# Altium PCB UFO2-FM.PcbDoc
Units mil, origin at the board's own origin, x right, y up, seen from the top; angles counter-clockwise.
Board outline 2125.98 x 1889.76 mil, 2 copper layers (Top Layer, Bottom Layer), stack 63.824 mil thick; 93 components, 51 nets, 265 pads, 112 vias.
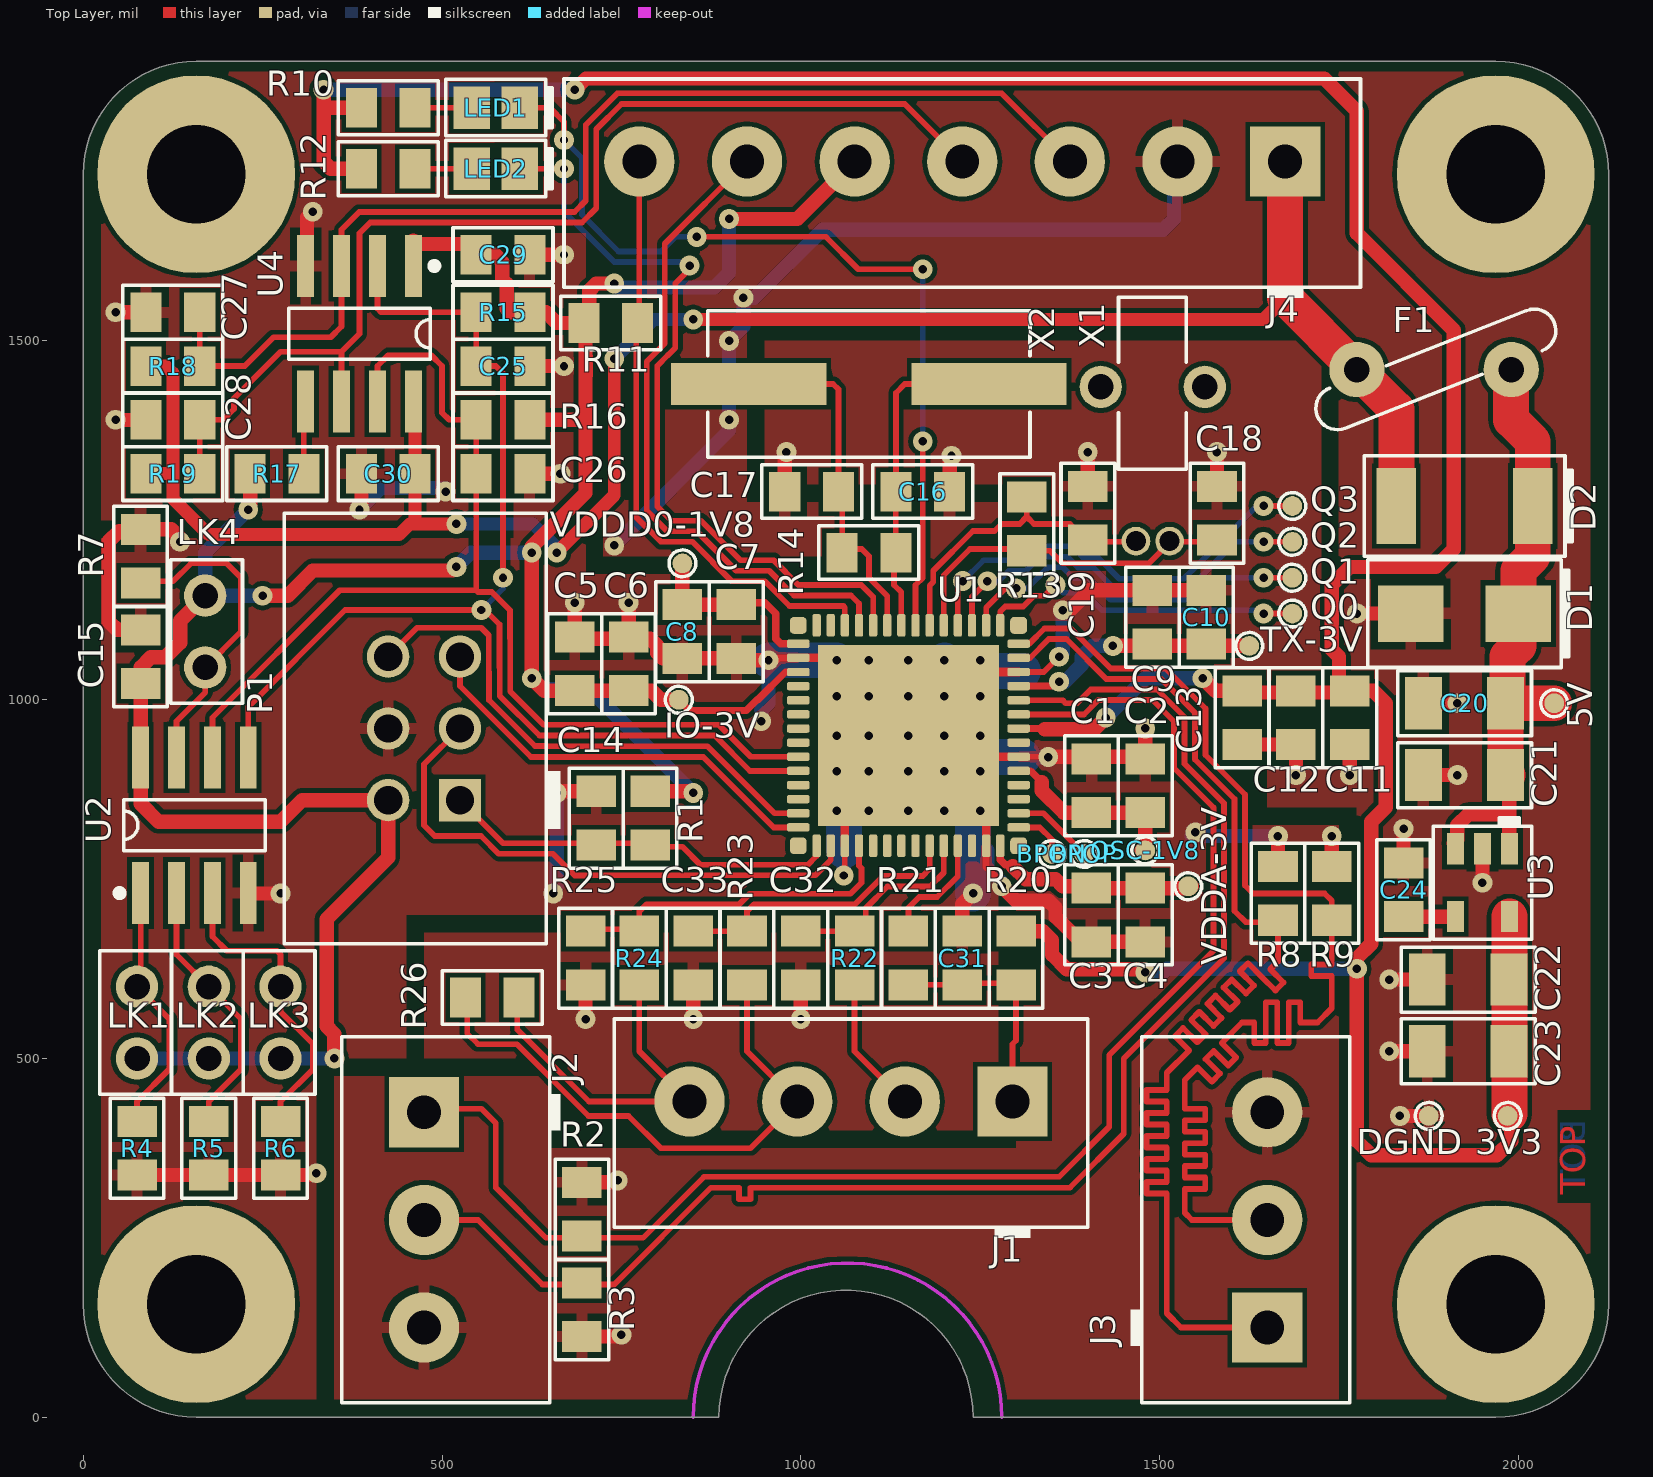
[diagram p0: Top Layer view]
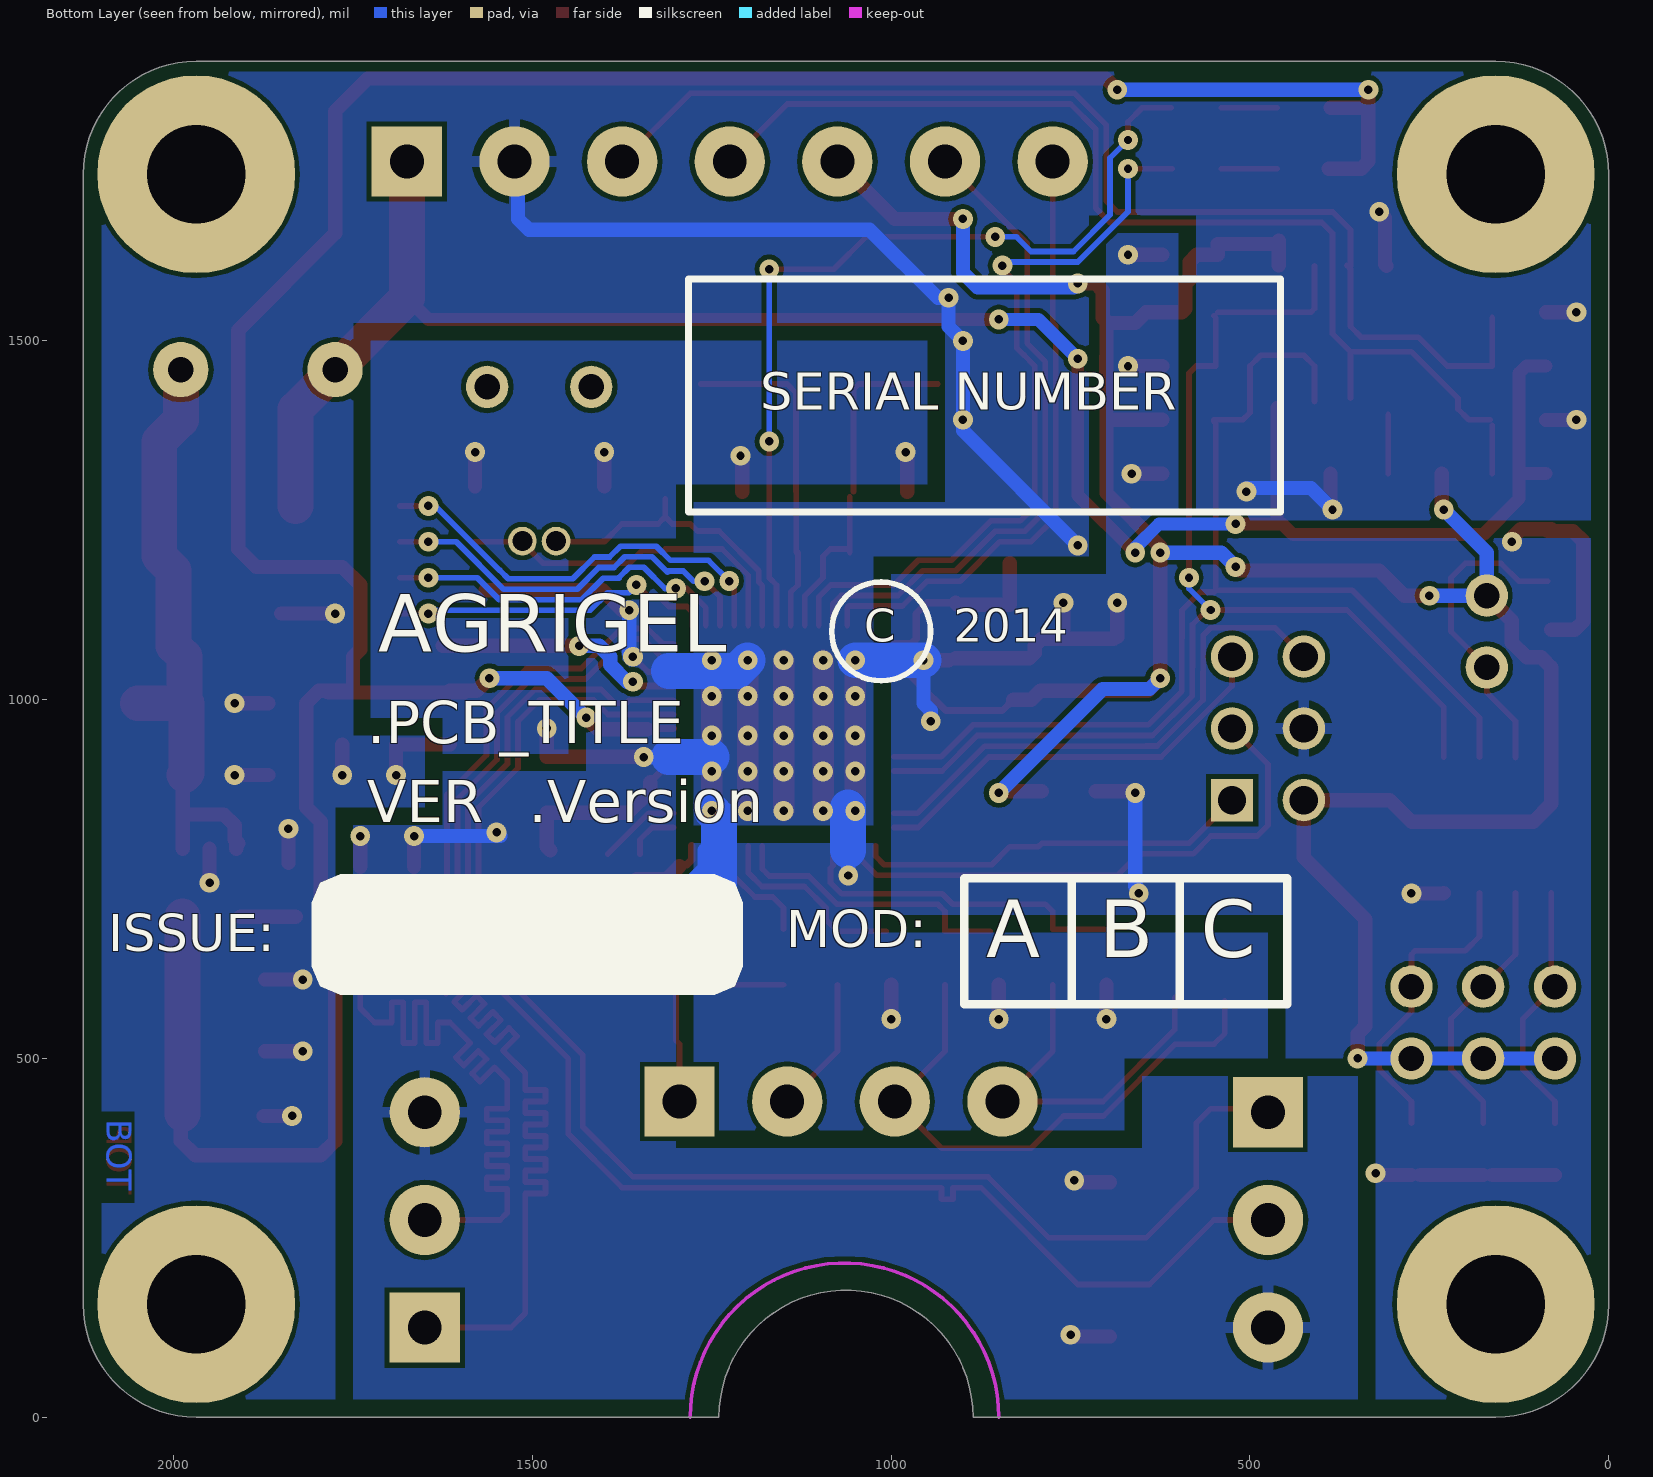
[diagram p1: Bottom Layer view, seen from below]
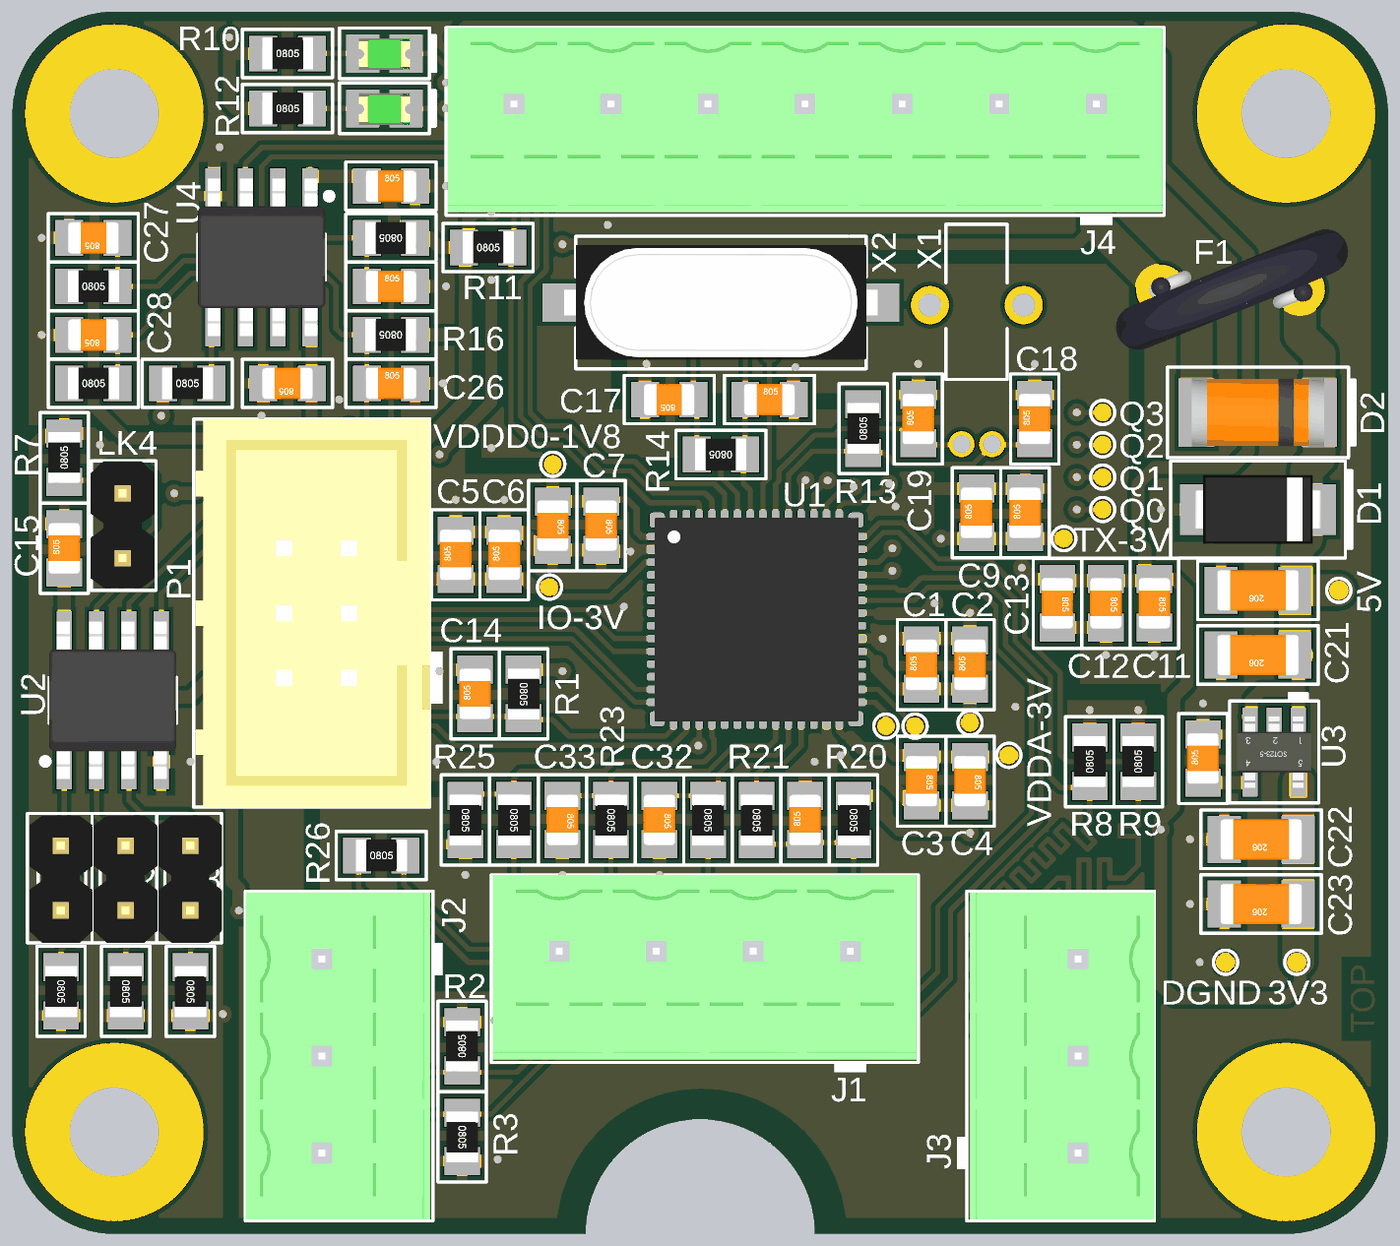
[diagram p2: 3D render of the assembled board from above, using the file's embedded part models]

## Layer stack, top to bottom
Top Layer: signal copper 1.4
Dielectric: prepreg 61.0236, FR-4, Dk 4.2
Bottom Layer: signal copper 1.4

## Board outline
0,157.48 ccw(c157.48,157.48) 157.48,0 157.48,0.01 885.83,0 cw(c1062.99,0) 1240.16,0 1968.5,0 ccw(c1968.5,157.48) 2125.98,157.48 2125.98,1732.28 ccw(c1968.5,1732.28) 1968.5,1889.76 157.48,1889.76 ccw(c157.48,1732.28) 0,1732.28

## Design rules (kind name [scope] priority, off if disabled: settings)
Clearance [All] p1: gap=6.69
ComponentClearance [All] p1: gap=0 collisioncheckmode=3 verticalgap=1 showdistances=FALSE
FabricationTestPointUsage TestPointUsage [All] p1: valid=0 allowmultiple=FALSE
FabricationTestpoint Testpoint [All] p1: side=3 testpointundercomponent=TRUE minsize=40 maxsize=100 preferedsize=60 minholesize=0 maxholesize=40 preferedholesize=32 testpointgrid=1 allowsidetop=TRUE allowsidebottom=TRUE usegrid=TRUE gridtolerance=0.01
HoleSize [All] p1: absolutevalues=TRUE maxlimit=196.85 minlimit=9.84 maxpercent=80.000 minpercent=20.000
Length "Schematic Length Constraint_3" [InNet('TX3')] p1: maxlimit=2050 minlimit=2030
Length "Schematic Length Constraint_2" [InNet('TX2')] p2: maxlimit=2050 minlimit=2030
Length "Schematic Length Constraint_1" [InNet('TX1')] p3: maxlimit=2050 minlimit=2030
Length "Schematic Length Constraint" [InNet('TX0')] p4: maxlimit=2050 minlimit=2030
PlaneClearance [All] p1: clearance=19.68
PolygonConnect PolygonConnect_1 [All vs IsNamedPolygon('Bot - DGND-Direct')] p1: connectstyle=Direct reliefconductorwidth=10 reliefentries=4 polygonreliefangle="90 Angle" airgapwidth=10
PolygonConnect PolygonConnectVia [All vs isvia] p2: connectstyle=Direct reliefconductorwidth=9.84 reliefentries=4 polygonreliefangle="90 Angle" airgapwidth=10
PolygonConnect [All] p3: connectstyle=Relief reliefconductorwidth=15.75 reliefentries=4 polygonreliefangle="90 Angle" airgapwidth=10
RoutingCorners [All] p1: cornerstyle=45-Degree minsetback=98.43 maxsetback=98.43
RoutingVias [All] p1: holewidth=11.81 width=27.56 viastyle="Through Hole" minholewidth=11.81 minwidth=27.56 maxholewidth=11.81 maxwidth=27.56
ShortCircuit LK5 [(InNet('DGND') AND InComponent('LK5'))] p1: allowed=TRUE
ShortCircuit LK6 [(InNet('DGND') AND InComponent('LK6'))] p2: allowed=TRUE
ShortCircuit LK7 [(InNet('DGND') AND InComponent('LK7'))] p3: allowed=TRUE
ShortCircuit LK8 [(InNet('DGND') AND InComponent('LK8'))] p4: allowed=TRUE
ShortCircuit LK9 [(InNet('DGND') AND InComponent('LK9'))] p5: allowed=TRUE
ShortCircuit [All] p6: allowed=FALSE
SilkToSolderMaskClearance SilkscreenOverComponentPads [IsPad] p1: minsilkscreentomaskgap=10 clearancetoexposedcopper=TRUE
SolderMaskExpansion [All] p1: expansion=1.97
Width "Width_High Power" [InNetClass('High Power')] p1: maxlimit=59.06 minlimit=19.68 preferedwidth=39.37
Width Width_Power [InNetClass('Power')] p2: maxlimit=39.37 minlimit=11.81 preferedwidth=19.68
Width [All] p3: maxlimit=78.74 minlimit=7.87 preferedwidth=7.87
20 further rules are at their usual default settings.

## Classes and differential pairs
component class UFO2-FM: VDDD0-1V8

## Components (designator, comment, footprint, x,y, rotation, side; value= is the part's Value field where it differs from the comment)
3V3 "TP-SMD-0.7MM_V" TP-SMD-0.7MM 1985,420 r90 top
5V "TP-SMD-0.7MM_V" TP-SMD-0.7MM 2050,995 r90 top
BPON "TP-SMD-0.7MM" TP-SMD-0.7MM 1350,785 r270 top
BPOP "TP-SMD-0.7MM" TP-SMD-0.7MM 1395,785 r270 top
C1 "4.7uF_C0805_10V_10%_X5R" CAPC0805X110N 1405,880 r90 top
C2 "100nF_C0805_50V_10%_X7R" CAPC0805X110N 1480,880 r90 top
C3 "4.7uF_C0805_10V_10%_X5R" CAPC0805X110N 1405,700 r270 top
C4 "100nF_C0805_50V_10%_X7R" CAPC0805X110N 1480,700 r270 top
C5 "4.7uF_C0805_10V_10%_X5R" CAPC0805X110N 685,1050 r90 top
C6 "100nF_C0805_50V_10%_X7R" CAPC0805X110N 760,1050 r90 top
C7 "4.7uF_C0805_10V_10%_X5R" CAPC0805X110N 910,1095 r270 top
C8 "100nF_C0805_50V_10%_X7R" CAPC0805X110N 835,1095 r270 top
C9 "4.7uF_C0805_10V_10%_X5R" CAPC0805X110N 1490,1115 r90 top
C10 "100nF_C0805_50V_10%_X7R" CAPC0805X110N 1565,1115 r90 top
C11 "4.7uF_C0805_10V_10%_X5R" CAPC0805X110N 1765,975 r270 top
C12 "4.7uF_C0805_10V_10%_X5R" CAPC0805X110N 1690,975 r270 top
C13 "100nF_C0805_50V_10%_X7R" CAPC0805X110N 1615,975 r270 top
C14 "100nF_C0805_50V_10%_X7R" CAPC0805X110N 715,835 r90 top
C15 "100nF_C0805_50V_10%_X7R" CAPC0805X110N 80,1060 r90 top
C16 "22pF_C0805_50V_10%_X7R" CAPC0805X110N 1170,1290 r0 top
C17 "22pF_C0805_50V_10%_X7R" CAPC0805X110N 1015,1290 r180 top
C18 "22pF_C0805_50V_10%_X7R" CAPC0805X110N 1580,1260 r90 top
C19 "22pF_C0805_50V_10%_X7R" CAPC0805X110N 1400,1260 r90 top
C20 "10uF_C1206_16V_5%_X7R" CAPC1206X178N 1925,995 r180 top
C21 "10uF_C1206_16V_5%_X7R" CAPC1206X178N 1925,895 r180 top
C22 "10uF_C1206_16V_5%_X7R" CAPC1206X178N 1930,610 r180 top
C23 "10uF_C1206_16V_5%_X7R" CAPC1206X178N 1930,510 r180 top
C24 "10nF_C0805_50V_10%_X7R" CAPC0805X110N 1840,735 r90 top
C25 "10nF_C0805_50V_10%_X7R" CAPC0805X110N 585,1465 r0 top
C26 "10nF_C0805_50V_10%_X7R" CAPC0805X110N 585,1315 r0 top
C27 "10nF_C0805_50V_10%_X7R" CAPC0805X110N 125,1540 r180 top
C28 "10nF_C0805_50V_10%_X7R" CAPC0805X110N 125,1390 r180 top
C29 "10nF_C0805_50V_10%_X7R" CAPC0805X110N 585,1620 r0 top
C30 "10nF_C0805_50V_10%_X7R" CAPC0805X110N 425,1315 r180 top
C31 "10nF_C0805_50V_10%_X7R" CAPC0805X110N 1225,640 r90 top
C32 "10nF_C0805_50V_10%_X7R" CAPC0805X110N 1000,640 r270 top
C33 "10nF_C0805_50V_10%_X7R" CAPC0805X110N 850,640 r270 top
D1 "SK110_SMA" SMA 1925,1120 r180 top
D2 "SM4007-DNF" DO-213AB 1925,1270 r180 top
DGND "TP-SMD-0.7MM_V" TP-SMD-0.7MM 1875,420 r180 top
F1 "MF-R050" MF-R110 1885,1460 r0 top
IO-3V "TP-SMD-0.7MM_V" TP-SMD-0.7MM 830,1000 r180 top
J1 "ECH381V-04P" ECH381V-04P 1070,440 r0 top
J2 "ECH381V-03P" ECH381V-03P 475,275 r90 top
J3 "ECH381V-03P" ECH381V-03P 1650,275 r270 top
J4 "ECH381V-07P" ECH381V-07P 1225,1750 r0 top
LED1 "GREEN_0805_SMD" LED0805-Green 575,1825 r180 top
LED2 "GREEN_0805_SMD" LED0805-Green 575,1740 r180 top
LK1 "Link-THP-2.54-2PIN" Link-THP-2.54-2PIN 75,550 r90 top
LK2 "Link-THP-2.54-2PIN" Link-THP-2.54-2PIN 175,550 r90 top
LK3 "Link-THP-2.54-2PIN" Link-THP-2.54-2PIN 275,550 r90 top
LK4 "Link-THP-2.54-2PIN" Link-THP-2.54-2PIN 170,1095 r270 top
OSC-1V8 "TP-SMD-0.7MM_V" TP-SMD-0.7MM 1480,790 r90 top
P1 "09185066324" 09185066324 475,960 r90 top
Q0 "TP-SMD-0.7MM" TP-SMD-0.7MM 1685,1120 r270 top
Q1 "TP-SMD-0.7MM" TP-SMD-0.7MM 1685,1170 r180 top
Q2 "TP-SMD-0.7MM" TP-SMD-0.7MM 1685,1220 r270 top
Q3 "TP-SMD-0.7MM" TP-SMD-0.7MM 1685,1270 r270 top
R1 "39K_R0805_1%" RESC0805X65N 790,835 r270 top
R2 "100R_R0805_1%" RESC0805X65N 695,290 r90 top
R3 "100R_R0805_1%" RESC0805X65N 695,150 r270 top
R4 "10K_R0805_1%" RESC0805X65N 75,375 r270 top
R5 "10K_R0805_1%" RESC0805X65N 175,375 r270 top
R6 "10K_R0805_1%" RESC0805X65N 275,375 r270 top
R7 "10K_R0805_1%" RESC0805X65N 80,1200 r90 top
R8 "100R_R0805_1%" RESC0805X65N 1665,730 r90 top
R9 "100R_R0805_1%" RESC0805X65N 1740,730 r90 top
R10 "3K_R0805_1%" RESC0805X65N 425,1825 r0 top
R11 "10K_R0805_1%" RESC0805X65N 735,1525 r0 top
R12 "3K_R0805_1%" RESC0805X65N 425,1740 r0 top
R13 "10M_R0805_1%" RESC0805X65N 1315,1245 r90 top
R14 "1M_R0805_1%" RESC0805X65N 1095,1205 r180 top
R15 "10K_R0805_1%" RESC0805X65N 585,1540 r180 top
R16 "10K_R0805_1%" RESC0805X65N 585,1390 r180 top
R17 "10K_R0805_1%" RESC0805X65N 270,1315 r0 top
R18 "10K_R0805_1%" RESC0805X65N 125,1465 r0 top
R19 "10K_R0805_1%" RESC0805X65N 125,1315 r0 top
R20 "0R[NEQ]_R0805_1%" RESC0805X65N 1300,640 r270 top
R21 "0R_R0805_1%" RESC0805X65N 1150,640 r270 top
R22 "2K7_R0805_1%" RESC0805X65N 1075,640 r270 top
R23 "2K7_R0805_1%" RESC0805X65N 925,640 r270 top
R24 "1K_R0805_0.1%" RESC0805X65N 775,640 r270 top
R25 "1K5_R0805_1%" RESC0805X65N 700,640 r270 top
R26 "0R[NEQ]_R0805_1%" RESC0805X65N 570,585 r0 top
TX-3V "TP-SMD-0.7MM_V" TP-SMD-0.7MM 1625,1075 r90 top
U1 "UFO2" QFN56-8x8-EP 1150,950 r0 top
U2 "24LC256-I/SN" SO8 155,825 r90 top
U3 "LP2992IM5X-5.0" SOT23-5 1950,745 r270 top
U4 "PCA9512AD" SO8 385,1510 r270 top
VDDA-3V "TP-SMD-0.7MM_V" TP-SMD-0.7MM 1540,740 r90 top
VDDD0-1V8 "TP-SMD-0.7MM_V" TP-SMD-0.7MM 835,1190 r90 top
X1 "32.768kHz" MMTF32 1490,1435 r0 top
X2 "XTAL_16.00MHz-ACT-HC49/US-SMX" HC49/US-SMX-4.2 1095,1440 r180 top

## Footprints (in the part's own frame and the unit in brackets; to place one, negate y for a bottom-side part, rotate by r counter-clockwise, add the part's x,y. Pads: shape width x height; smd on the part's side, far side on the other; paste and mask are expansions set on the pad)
09185066324 [mil] "09185066324 2.54mm"
  rect 59x59 hole 39.37: 1(-100,-50)
  round 59 hole 39.37: 2(-100,50) 3(0,-50) 4(0,50) 5(100,-50) 6(100,50)
  silkscreen extent -300,-190 300,195, body extent -300,-170 300,192, height 373
CAPC0805X110N [mm] "Chip Capacitor, 0805, 2-Leads, Body 2.0x1.3mm, IPC Medium Density"
  rect 1.1x1.4 smd paste+0 mask+0.05: 1(-0.95,0) 2(0.95,0)
  silkscreen extent -1.77,-0.95 1.77,0.95, body extent -1,-0.62 1,0.63, height 1.11
CAPC1206X178N [mm] "Chip Capacitor, 1206, 2-Leads, Body 3.2x1.6mm, IPC Medium Density"
  rect 1.3x1.85 smd paste+0 mask+0.05: 1(-1.45,0) 2(1.45,0)
  silkscreen extent -2.37,-1.15 2.37,1.15, body extent -1.6,-0.8 1.6,0.8, height 1.77
DO-213AB [mil] "DO-213AB 5.0x2.5mm"
  rect 55x106 smd mask+1: 1(-95,0) 2(95,0)
  silkscreen extent -150,-70 140,70, body extent -102,-53 102,53, height 106
ECH381V-03P [mil] "ECH381V-03P 12.22x7.0mm"
  rect 98x98 hole 47.24: 1(150,0)
  round 98 hole 47.24: 2(0,0) 3(-150,0)
  silkscreen extent -255,-190 255,115, body extent -252,-170 252,115, height 362
ECH381V-04P [mil] "ECH381V-04P 19.84x7.0mm"
  rect 98x98 hole 47.24: 1(225,0)
  round 98 hole 47.24: 2(75,0) 3(-75,0) 4(-225,0)
  silkscreen extent -330,-190 330,115, body extent -327,-170 327,115, height 362
ECH381V-07P [mil] "ECH381V-07P 31.27x7.0mm"
  rect 98x98 hole 47.24: 1(450,0)
  round 98 hole 47.24: 2(300,0) 3(150,0) 4(0,0) 5(-150,0) 6(-300,0) 7(-450,0)
  silkscreen extent -555,-190 555,115, body extent -552,-170 552,115, height 362
HC49/US-SMX-4.2 [mm] "XTAL-HC49/US-SMX, 2-Leads, Body 11.1x4.83mm (max), Pitch 4.3mm"
  rect 5.5x1.5 smd paste+0 mask+0.025: 1(-4.25,0) 2(4.25,0)
  silkscreen extent -5.7,-2.6 5.7,2.6, body extent -6.15,-2.25 6.15,2.25, height 5.18
LED0805-Green [mm] "LED, 0805, 2-Leads, Body 2.0x1.3mm, IPC Medium Density"
  rect 1.3x1.5 smd paste+0 mask+0.025: 1(-0.85,0) 2(0.85,0)
  silkscreen extent -2,-1 1.77,0.99, body extent -1.01,-0.6 1.01,0.65, height 1.2
Link-THP-2.54-2PIN [mil] "Link THP 2.54mm"
  round 59 hole 35.43: 1(-50,0) 2(50,0)
  silkscreen extent -100,-48 100,52, body extent -100,-49 96,49, height 323
MF-R110 [mil] "MF-R110 8.9x3.0mm"
  round 77 hole 35.43: 1(-110,0) 2(105,0)
  silkscreen extent -167,-84 167,84, body extent -200,-127 200,127, height 624
MMTF32 [mil] "MMTF 6.0x2.0mm"
  round 40 hole 27.56: 1(-23,-214) 2(24,-214)
  round 59 hole 35.43: M1(-72,1) M2(73,1)
  silkscreen extent -47,-114 47,126, body extent -47,-226 47,126, height 94
QFN56-8x8-EP [mm] "QFN 56 8.0x8.0mm"
  rrect50% 0.8x0.3 smd mask+0.025: 1(-3.9,3.25) 2(-3.9,2.75) 3(-3.9,2.25) 4(-3.9,1.75) 5(-3.9,1.25) 6(-3.9,0.75) 7(-3.9,0.25) 8(-3.9,-0.25) 9(-3.9,-0.75) 10(-3.9,-1.25) 11(-3.9,-1.75) 12(-3.9,-2.25) 13(-3.9,-2.75) 14(-3.9,-3.25) 29(3.9,-3.25) 30(3.9,-2.75) 31(3.9,-2.25) 32(3.9,-1.75) 33(3.9,-1.25) 34(3.9,-0.75) 35(3.9,-0.25) 36(3.9,0.25) 37(3.9,0.75) 38(3.9,1.25) 39(3.9,1.75) 40(3.9,2.25) 41(3.9,2.75) 42(3.9,3.25)
  rrect50% 0.3x0.8 smd mask+0.025: 15(-3.25,-3.9) 16(-2.75,-3.9) 17(-2.25,-3.9) 18(-1.75,-3.9) 19(-1.25,-3.9) 20(-0.75,-3.9) 21(-0.25,-3.9) 22(0.25,-3.9) 23(0.75,-3.9) 24(1.25,-3.9) 25(1.75,-3.9) 26(2.25,-3.9) 27(2.75,-3.9) 28(3.25,-3.9) 43(3.25,3.9) 44(2.75,3.9) 45(2.25,3.9) 46(1.75,3.9) 47(1.25,3.9) 48(0.75,3.9) 49(0.25,3.9) 50(-0.25,3.9) 51(-0.75,3.9) 52(-1.25,3.9) 53(-1.75,3.9) 54(-2.25,3.9) 55(-2.75,3.9) 56(-3.25,3.9)
  rect 6.4x6.4 smd paste-3.5 mask+0.025: 57(0,0)
  rrect50% 0.6x0.6 smd mask+0.025: C1(-3.9,3.9) C2(-3.9,-3.9) C3(3.9,-3.9) C4(3.9,3.9)
  body extent -4,-4 4,4, height 0.77
RESC0805X65N [mm] "Chip Resistor, 0805, 2-Leads, Body 2.0x1.3mm, IPC Medium Density"
  rect 1.1x1.4 smd paste+0 mask+0.05: 1(-0.95,0) 2(0.95,0)
  silkscreen extent -1.77,-0.95 1.77,0.95, body extent -0.99,-0.62 1.01,0.63, height 0.6
SMA [mil] "SMA 5.6x2.95mm"
  rect 91x79 smd mask+0.98: 1(-75,0.08) 2(75,0.08)
  silkscreen extent -145,-75 135,75, body extent -98,-53 98,53, height 85
SO8 [mm] "SOIC, 8-Leads, Body 5.0x4.0mm (max), Pitch 1.27mm, IPC Medium Density"
  rect 2.2x0.6 smd paste+0 mask+0.05: 1(-2.4,1.905) 2(-2.4,0.635) 3(-2.4,-0.635) 4(-2.4,-1.905) 5(2.4,-1.905) 6(2.4,-0.635) 7(2.4,0.635) 8(2.4,1.905)
  silkscreen extent -2.52,-2.5 0.9,2.77, body extent -3.1,-2.5 3.1,2.5, height 1.78
SOT23-5 [mm] "SOT23, 5-Leads, Body 3.0x3.0mm (max), Pitch 0.95mm, IPC Medium Density"
  rect 1.1x0.6 smd paste+0 mask+0.05: 1(-1.2,0.95) 2(-1.2,0) 3(-1.2,-0.95) 4(1.2,-0.95) 5(1.2,0.95)
  silkscreen extent -2.3,-1.75 2,1.75, body extent -1.4,-1.45 1.4,1.45, height 1.14
TP-SMD-0.7MM [mm] "Test Point, SMD, 0.7mm"
  round 0.7 smd paste-1 mask+0.025: 1(0,0)
  silkscreen extent -0.47,-0.48 0.47,0.47, body extent -0.35,-0.35 0.35,0.35, height 0.01

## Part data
3V3 5V BPON BPOP DGND IO-3V OSC-1V8 Q0 Q1 Q2 Q3 TX-3V VDDA-3V VDDD0-1V8: "Test Point Surface Mount 0.7mm Pad"
C1 C3 C5 C7 C9 C11 C12: library part 4.7uF_0805N_10V_10%_X5R_V, "Cap Ceramic X5R"
C2 C4 C6 C8 C10 C13 C14 C15: library part 100nF_0805N_50V_10%_X7R_V, "Cap Ceramic X7R"
C16 C17 C18 C19: library part 22pF_0805N_50V_10%_X7R_V, "Cap Ceramic X7R"
C20 C21 C22 C23: library part 10uF_1206N_16V_5%_X7R_V, "Cap Ceramic X7R"
C24 C25 C26 C27 C28 C29 C30 C31 C32 C33: library part 10nF_0805N_50V_10%_X7R_V, "Cap Ceramic X7R"
D1: library part SK110_SMA_V, "Diode Schottky Rectifier 1Amp 100V"
D2: library part SM4007_H-DNF, "Diode Rectifier 1Amp 1000V - Do no Fit"
F1: library part PolyFuse-MF-R050, "PTC Resettable Fuse 500mA 60V"
J1 J2 J3 J4: "Header Pluggable 3.81mm Vertical"
LED1 LED2: library part GREEN_0805_SMD_H, "LED SMD 0805 Green"
LK1 LK2 LK3 LK4: "Link THP Open 2.54mm"
P1: "Header Box Male Straight 2.54mm Pitch"
R1: library part 39K_0805_V, "Resistor Chip SMD"
R2 R3 R8 R9: library part 100R_0805_V, "Resistor Chip SMD"
R4 R5 R6 R7 R11 R15 R16 R17 R18 R19: library part 10K_0805_V, "Resistor Chip SMD"
R10 R12: library part 3K_0805_H, "Resistor Chip SMD"
R13: library part 10M_0805_H, "Resistor Chip SMD"
R14: library part 1M_0805_H, "Resistor Chip SMD"
R20 R26: library part 0R_0805_H-DNF, "Resistor Chip SMD - Do not Fit"
R21: library part 0R_0805_H, "Resistor Chip SMD"
R22 R23: library part 2K7_0805_H, "Resistor Chip SMD"
R24: library part 1K_0805_H-0.1%, "Resistor Chip SMD"
R25: library part 1K5_0805_V, "Resistor Chip SMD"
U1: library part UFO2_QFN56, "IC D-Flow ASIC"
U2: library part 24LC256-I/SN-SO8, "IC 256K I2C Serial EEPROM"
U3: library part LP2992IM5X-5.0_SOT23-5N, "Voltage Regulator Ultra LDO 250mA"
U4: library part PCA9512AD_SO8, "IC Level-Shifting I2C Bus and SMBus Buffer"
X1: library part XTAL_32.768kHz_MMTF32, "Crystal - MMTF32"
X2: "Crystal - ACT HC49/US-SMX"

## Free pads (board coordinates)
  round 275.59 hole 137.8 unplated mask+1: 0(157.48,157.48) 1(1968.5,157.48) 2(1968.5,1732.28) 3(157.48,1732.28)

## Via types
v1: diameter 27.56, hole 11.81, Top Layer to Bottom Layer, tented both sides, 112 vias

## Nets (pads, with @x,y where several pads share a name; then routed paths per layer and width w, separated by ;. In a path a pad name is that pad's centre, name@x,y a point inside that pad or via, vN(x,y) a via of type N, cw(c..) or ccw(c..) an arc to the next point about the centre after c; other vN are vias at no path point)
+3V3: 3V3.1 C11.1 C12.1 C13.1 C22.1 C23.1 R10.1 R12.1 R20.1 U1.36 U3.5 | length 4992.2
  Top Layer w10: U1.36 1341.96,959.84 ; 1341.96,955.06 1345.21,955.06 1348.99,958.83
  Top Layer w20: v1(335,1850) 335,1825 ; R10.1 335,1825 ; R12.1@390,1740 R12.1 345,1740 335,1750 335,1825 ; v1(685,1850) 700.69,1865.69 1729.31,1865.69 1775,1820 1775,1650 1910,1515 1910,1210 1885,1185 1765,1185 1740,1160 1740,1070 1750,1060 1750,1012.4 C11.1 1797.6,1012.4 1815,995 1815,850 1795,830 1795,660 1775,640 v1(1775,625) 1775,385 1795,365 1970,365 1990,385 3V3.1@1990,425 ; R20.1 1337.6,677.4 1350,665 1350,644.78 1370.53,624.25 1475.75,624.25 v1(1480,620) ; 1340,958.83 1348.99,958.83 1408.83,958.83 v1(1425,975) ; v1(1560,1030) 1577.6,1012.4 C13.1 ; C13.1@1595,1010 C11.1@1784.53,1010
  Top Layer w50: 3V3.1@1987.4,422.4 U3.5
  Bottom Layer w20: v1(335,1850) v1(685,1850) ; v1(1425,975) 1480,1030 v1(1560,1030) ; v1(1480,620) 1505,620 1510,625 v1(1775,625)
+5V: 5V.1 C20.1 C21.1 D1.1 D2.1 F1.2 U3.1 U3.3 | length 877.9
  Top Layer w20: U3.3@1910,800 U3.3@1912.6,802.6 ; U3.3 U3.3@1912.6,802.6 ; C21.1@1980,890 1987.4,882.6 1987.4,840 ; C21.1 C21.1@1985,895 ; U3.1 1987.4,840 ; U3.3@1912.6,802.6 1915,805 1915,825 1930,840 1987.4,840
  Top Layer w50: C20.1 1982.09,897.91 C21.1@1985,895 ; F1.2 1990,1390 2020,1360 D2.1 2020,1200 2000,1180 D1.1 2000,1075 1985,1060 1985,995 5V.1
DGND: C1.2 C2.2 C3.2 C4.2 C5.2 C6.2 C7.2 C8.2 C9.2 C10.2 C11.2 C12.2 C13.2 C14.2 C15.2 C16.2 C17.2 C18.2 C19.2 C20.2 C21.2 C22.2 C23.2 C24.2 C25.2 C26.2 C27.2 C28.2 C29.2 C30.2 C31.2 C32.2 C33.2 D1.2 DGND.1 J2.3 J3.3 J4.2 P1.4 R2.2 R3.2 R4.2 R5.2 R6.2 R7.2 R8.2 R9.2 R25.2 U1.2 U1.17 U1.27 U1.34 U1.40 U1.57 U2.4 U3.2 U4.4 | length 6951.9
  Top Layer w8: v1(1060,755) 1061.42,756.42 U1.17 ; U1.34 v1@1350.47,920.47 ; U1.40 1338.58,1038.58 v1(1360,1060)
  Top Layer w10: v1(955,1055) 965,1055 968.27,1058.27 U1.2 ; U1.27 1258.27,766.73 v1@1275,750
  Top Layer w12: U1.2 U1.57@1043.27,1058.27 ; U1.17 U1.57@1061.42,833.58 ; U1.57@1251.42,1038.58 U1.40 ; U1.27 U1.57@1258.27,836.73 ; U1.57@1274.53,920.47 U1.34
  Top Layer w19.68: v1(45,1390) C28.2 ; v1(45,1540) C27.2 ; U4.4 311.81,1606.3 311.81,1671.81 v1(320,1680) ; v1(385,1265) 387.6,1267.6 C30.2 ; C13.2 C12.2@1687.4,937.6 ; v1(1690,895) C12.2 ; v1(1765,895) C11.2 ; v1(1775,1120) 1775.08,1119.92 D1.2 ; v1(1820,510) C23.2 ; v1(1820,610) C22.2 ; v1(1835,420) DGND.1 ; C24.2 v1(1840,820) ; C21.2 v1(1915,895) ; C20.2 v1(1915,995) ; v1(1950,745) U3.2
  Top Layer w20: R4.2 R5.2@162.4,337.6 ; C15.2 47.4,1097.4 35.75,1109.06 35.75,1220.75 50,1235 R7.2@85,1235 ; R7.2 122.6,1237.4 135,1225 v1(135,1220) ; R5.2 R6.2@262.6,337.6 ; U2.4 230.51,730 v1(275,730) ; R6.2 322.6,337.6 v1(325,340) ; C26.2 v1(665,1315) ; C25.2 v1(670,1465) ; C29.2 v1(670,1620) ; v1(660,870) 657.6,872.4 C14.2 ; C5.2 C5.2@685,1090 ; v1(685,1135) C5.2@685,1090 ; R3.2 747.6,112.6 v1(750,115) ; R2.2 742.4,327.4 v1(745,330) ; v1(700,555) R25.2 ; C6.2 v1(760,1135) ; C8.2 807.4,1057.6 800,1065 800,1075 790,1085 690,1085 C5.2@685,1090 ; C8.2@837.6,1057.6 C7.2 ; v1(850,555) C33.2 ; C7.2@920,1055 v1(955,1055) ; C17.2 977.6,1342.6 v1(980,1345) ; v1(1000,555) C32.2 ; C16.2 1207.4,1337.4 v1(1210,1340) ; C31.2 1225,715 v1(1240,730) ; v1(1280,740) 1300,720 1345,720 1355,710 1355,697.75 1387.75,665 1405,665 1407.4,662.6 C4.2 ; v1(1345,920) 1350,920 1350.47,920.47 1480,920.47 v1(1480,960) ; v1(1365,1124.69) 1374.69,1124.69 1402.4,1152.4 C9.2 C10.2 ; C19.2 v1(1400,1345) ; C18.2 v1(1580,1345) ; R8.2 v1(1665,810) ; R9.2 v1(1740,810)
  Top Layer w30: v1(1050,845) v1(1050,900) v1(1050,950) v1(1050,1005) v1(1050,1055) ; v1(1095,845) v1(1095,900) v1(1095,950) v1(1095,1005) v1(1095,1055) ; v1(1150,845) v1(1150,900) v1(1150,950) v1(1150,1005) v1(1150,1055) ; v1(1200,845) v1(1200,900) v1(1200,950) v1(1200,1005) v1(1200,1055) ; v1(1250,845) v1(1250,900) v1(1250,950) v1(1250,1005) v1(1250,1055)
  Bottom Layer w10: v1(955,1055) v1@960,1060
  Bottom Layer w19.68: v1(385,1265) 415,1295 505,1295 v1(505,1290) ; v1(740,1215) 900,1375 v1(900,1390) v1(900,1500) 920,1520 v1(920,1560) 935,1560 1030,1655 1505,1655 1520,1670 1520,1745 J4.2
  Bottom Layer w20: v1(655,730) 655,735 660,740 v1(660,870) ; v1(945,970) 945,985 955,995 v1(955,1055) ; v1@960,1060 990,1060 ; v1(1060,755) 1060,790 ; 1260,790 1260,765 1280,745 v1(1280,740) ; 1310,920 v1(1345,920) ; v1@1365,1065 v1(1365,1124.69) ; v1(1550,815) 1545,810 v1(1665,810)
  Bottom Layer w50: v1(955,1055) v1(1050,1055) ; 1060,790 v1@1060,850 ; v1(1200,1055) 1215,1040 1310,1040 ; v1(1240,730) 1240,835 v1(1250,845) ; 1250,920 1310,920
MODE-BIT0: LED1.1 U1.49 | length 1231.7
  Top Layer w8: LED1.1@610,1825 650,1825 670,1805 v1(670,1780) ; v1(855,1645) 1035,1645 1080,1600 v1(1170,1600) ; U1.49 1159.84,1159.84 1170,1170 v1(1170,1360)
  Bottom Layer w8: v1(670,1780) 695,1755 695,1675.78 746.09,1624.69 805,1624.69 825.31,1645 v1(855,1645) ; v1(1170,1360) v1(1170,1600)
MODE-BIT1: LED2.1 U1.52 | length 1076.9
  Top Layer w8: LED2.1 v1@665,1740 ; v1(845,1605) 850,1605 825,1580 825,1490 815.22,1480.22 814.98,1480.22 800,1465.24 800,1269.39 820,1249.39 861.09,1249.39 916.09,1194.39 962.17,1194.39 996.56,1160 1084.22,1160 1100.79,1143.43 U1.52
  Bottom Layer w8: v1(670,1740) 670,1680 740,1610 840,1610 v1(845,1605)
NetBPON_1: BPON.1 U1.29 | length 73.5
  Top Layer w8: U1.29 1332.95,822.05 1350,805 BPON.1
NetBPOP_1: BPOP.1 U1.30 | length 115
  Top Layer w8: U1.30 1338.27,841.73 BPOP.1
NetC16_1: C16.1 R14.1 U1.50 X2.1 | length 468.2
  Top Layer w8: R14.1@1130,1205 1130,1160 1140.16,1149.84 U1.50 ; R14.1 C16.1@1132.4,1292.4 ; C16.1 1132.6,1427.6 1145,1440 X2.1 X2.1@1265,1440
NetC17_1: C17.1 R14.2 U1.51 X2.2 | length 486.6
  Top Layer w8: X2.2@935,1440 1045,1440 1052.4,1432.6 C17.1 ; R14.2 C17.1@1057.6,1282.4 ; R14.2@1060,1210 1085,1210 1095,1200 1095,1170 1120.47,1144.53 U1.51
NetC18_1: C18.1 R13.1 U1.47 X1.2 | length 485.5
  Top Layer w8: U1.47 1199.21,1125 1199.39,1125.17 1199.39,1173.61 1235.78,1210 R13.1@1315,1210 ; R13.1 1347.4,1207.6 1365,1190 1485,1190 1515,1220 C18.1@1580,1220
NetC19_1: C19.1 R13.2 U1.48 X1.1 | length 433.5
  Top Layer w8: U1.48 1179.53,1158.75 1184.69,1163.91 1184.69,1179.69 1240,1235 1270,1235 1280,1245 1305,1245 1315,1255 ; R13.2@1315,1280 1315,1255 ; C19.1@1400,1220 1375,1245 1325,1245 1315,1255 ; C19.1@1401.3,1221.3 1402.6,1220 X1.1@1470,1220
NetC24_1: C24.1 U3.4 | length 77.4
  Top Layer w20: C24.1@1830,697.6 C24.1 U3.4@1907.4,697.6
NetC31_1: C31.1 J1.1 R20.2 R21.2 | length 313.1
  Top Layer w8: R21.2 1222.6,602.6 1225,605 R20.2@1300,605 ; J1.1 1295,520 1300,525 R20.2@1300,600
NetJ1_2: J1.2 R22.2 | length 191.6
  Top Layer w8: R22.2 1075,510 J1.2
NetJ1_3: J1.3 R23.2 R26.1 | length 787.7
  Top Layer w8: R26.1@535,580 535,535 550,520 604.22,520 704.22,420 760,420 805,375 930,375 J1.3 ; R23.2 925,510 990,445 J1.3@995,445
NetJ1_4: J1.4 R24.2 R26.2 | length 518
  Top Layer w8: R26.2@605,585 605,540 705,440 J1.4 775,510 R24.2
NetLED1_2: LED1.2 R10.2 | length 77.6
  Top Layer w8: R10.2 LED1.2@540,1825
NetLED2_2: LED2.2 R12.2 | length 77.6
  Top Layer w8: R12.2 LED2.2@540,1740
NetLK1_2: LK1.2 R4.1 U2.1 | length 359.9
  Top Layer w8: R4.1@75,410 R4.1 75,440 120,485 120,555 LK1.2 80,605 U2.1
NetLK2_2: LK2.2 R5.1 U2.2 | length 376.4
  Top Layer w8: U2.2 130,645 LK2.2 220,555 220,485 175,440 R5.1 R5.1@175,410
NetLK3_2: LK3.2 R6.1 U2.3 | length 438.1
  Top Layer w8: U2.3 180,670 200,650 270,650 275,645 LK3.2 275,565 320,520 320,485 275,440 R6.1 R6.1@275,410
NetLK4_2: LK4.2 R7.1 U2.7 | length 441.4
  Top Layer w8: R7.1@85,1165 125,1165 150,1190 200,1190 220,1170 220,1095 LK4.2 170,1010 130,970 U2.7
NetQ0_1: Q0.1 U1.43 | length 458.4
  Top Layer w8: U1.43 1277.95,1122.95 1285,1130 1310,1130 1324.93,1144.93 1339.93,1144.93 v1(1355,1160) ; v1(1645,1120) Q0.1
  Bottom Layer w8: v1(1355,1160) 1365.83,1149.17 1395,1149.17 1419.58,1124.59 1640.41,1124.59 v1(1645,1120)
NetQ1_1: Q1.1 U1.44 | length 506.6
  Top Layer w8: U1.44 1258.27,1128.27 1285,1155 v1(1300,1155) ; v1(1645,1170) Q1.1
  Bottom Layer w8: v1(1300,1155) 1315.39,1155 1344.86,1184.47 1365.14,1184.47 1379.47,1170.14 1379.47,1169.39 1401.39,1169.39 1431.5,1139.28 1546.23,1139.28 1576.95,1170 v1(1645,1170)
NetQ2_1: Q2.1 U1.45 | length 557
  Top Layer w8: U1.45 1238.58,1143.58 v1(1260,1165) ; v1(1645,1220) Q2.1
  Bottom Layer w8: v1(1260,1165) 1275.39,1165 1289.86,1179.47 1310.14,1179.47 1311.92,1177.69 1333.39,1199.17 1371.22,1199.17 1386.31,1184.08 1407.48,1184.08 1437.58,1153.98 1540.14,1153.98 1606.17,1220 v1(1645,1220)
NetQ3_1: Q3.1 U1.46 | length 604.8
  Top Layer w8: U1.46 1218.9,1158.9 1225.36,1165.36 v1(1225.75,1165.36) ; v1(1645,1270) Q3.1
  Bottom Layer w8: v1(1225.75,1165.36) 1254.56,1194.17 1307.61,1194.17 1327.3,1213.86 1377.31,1213.86 1392.4,1198.77 1413.56,1198.77 1443.67,1168.67 1533.67,1168.67 1545,1180 ; 1545.2,1179.8 1635.39,1270 v1(1645,1270)
NetR17_2: R17.2 U4.5 | length 82.4
  Top Layer w8: R17.2 U4.5@307.4,1397.4
NRESET: C14.1 P1.1 R1.2 U1.15 | length 553.7
  Top Layer w8: P1.1 585,800 790,800 795,795 835,795 860,770 1010,770 1022.05,782.05 U1.15
RTD_0: R24.1 R25.1 U1.18 | length 479
  Top Layer w8: R25.1@700,680 775,680 775,705 785,715 914.22,715 928.91,729.69 1069.3,729.69 1084.47,744.86 1084.47,765.14 1081.1,768.51 U1.18
RTD_5: C33.1 R23.1 U1.23 | length 401.7
  Top Layer w8: C33.1@862.4,677.4 R23.1 925,705 935,715 1075.39,715 1114.77,754.39 1170,754.39 1179.53,763.91 U1.23
RTD_6: C32.1 R22.1 U1.24 | length 272.7
  Top Layer w8: C32.1@1007.4,677.4 R22.1 1090.58,692.98 1090.58,709.42 1120.86,739.69 1180,739.69 1199.21,758.91 U1.24
RTD_I: R21.1 U1.25 | length 159.6
  Top Layer w8: R21.1@1150,680 1150,710 1165,725 1190,725 1218.9,753.9 U1.25
RXD0: J4.7 R11.2 U1.54 | length 865.4
  Top Layer w8: J4.7 775,1525 770.61,1520.61 770.61,1254.39 805,1220 848.91,1220 903.91,1165 950,1165 984.39,1130.61 1059.39,1130.61 1061.42,1128.58 U1.54
SCL: C26.1 R16.2 U1.9 U2.6 U4.7 | length 1616.8
  Top Layer w8: U2.6@180,920 180,975 357.4,1152.4 547.6,1152.4 ; U4.7 410,1465 425,1480 485,1480 500,1465 500,1400 510,1390 R16.2 ; C26.1 547.6,1152.4 ; C26.1@547.6,1317.4 R16.2 ; R16.2@550,1387.6 R16.2 ; R16.2@550,1390 R16.2 ; U1.9 930.31,920.47 885.78,965 641.56,965 595,1011.56 595,1085 594.69,1085.31 594.69,1124.69 569.39,1150 550,1150 547.6,1152.4
SCLI: C28.1 J4.4 R19.2 U4.6 | length 1563.2
  Top Layer w8: R19.2 C28.1@162.4,1382.6 ; C28.1@165,1390 195,1390 210,1405 210,1420 275,1485 360,1485 ; U4.6@360,1420 360,1485 ; J4.4 1145,1830 750,1830 715,1795 715,1685 695,1665 400,1665 385,1650 385,1510 360,1485
SDA: C25.1 R15.2 U1.10 U2.5 U4.2 | length 1699.9
  Top Layer w8: U2.5@230,920 230,990 365,1125 v1(555,1125) 560,1125 580,1105 580,1045 580.31,1044.69 580.31,1005.47 635.78,950 880,950 929.21,900.79 U1.10 ; U4.2 410,1545 415,1540 R15.2@545,1540 ; R15.2@550,1535 547.6,1532.6 C25.1 575,1465 585,1455 v1(585,1170) v1@585,1165
  Bottom Layer w8: v1(555,1125) 585,1155 v1(585,1170)
SDAI: C27.1 J4.3 R18.2 U4.3 | length 1620.6
  Top Layer w8: C27.1@162.4,1532.6 R18.2 225,1465 265,1505 345,1505 360,1520 360,1600 U4.3@365,1605 ; U4.3 360,1655 384.69,1679.69 684.69,1679.69 700.31,1695.31 700.31,1801.09 744.22,1845 1280,1845 J4.3
TCK: P1.6 U1.13 | length 747.8
  Top Layer w8: P1.6 465.19,1100.19 554.81,1100.19 565.19,1089.81 565.19,1060 565.31,1059.89 565.31,1038.61 ; 565.61,1038.61 565.61,999.39 629.69,935.31 644.69,935.31 645,935 870,935 963.27,841.73 U1.13
TDA: P1.5 U1.14 | length 598.9
  Top Layer w8: P1.5@525,1065 P1.5 525,1019.22 623.91,920.31 863.91,920.31 962.17,822.05 U1.14
TST: P1.3 U1.16 | length 780
  Top Layer w8: P1.3 475,910 475,825 490,810 554.22,810 578.91,785.31 654.69,785.31 685,755 705,755 ; 705,755.31 1020.31,755.31 1041.73,776.73 U1.16
TX0: J2.1 R2.1 U1.37 | length 2036
  Top Layer w8: J2.1@470,430 475,430 555,430 575,410 575,320 645,250 695,250 780,250 865,335 1360,335 1430,405 1430,505 1575,650 1575,849.61 1520,904.61 1520,969.61 1490.14,999.47 1414.47,999.47 1394.53,979.53 U1.37
TX1: J2.2 R3.1 U1.38 | length 2049.2
  Top Layer w8: J2.2 550,275 640,185 695,185 740,185 875,320 914,320 914,304 930,304 930,320 1375,320 1450,395 1450,500 1589.69,639.69 1589.69,855.7 1534.69,910.7 1534.69,975.7 1496.22,1014.17 1404.17,1014.17 1385.19,995.19 1369.03,995.19 1365.01,999.21 U1.38
TX2: J3.1 R8.1 U1.41 | length 2040
  Top Layer w8: U1.41 1319.35,1058.27 1345.56,1084.47 1370.14,1084.47 1425.75,1028.86 1502.31,1028.86 1549.39,981.78 1549.39,916.78 1604.39,861.78 1604.39,705.61 1620,690 1665,690 1665,635 1654.34,624.34 1672.81,605.87 1661.5,594.56 1643.03,613.03 1623.18,632.88 1611.86,621.57 1631.72,601.72 1620.4,590.4 1600.55,610.25 1589.24,598.94 1609.09,579.09 1597.77,567.77 1577.92,587.63 1566.61,576.31 1586.46,556.46 1575.15,545.15 1555.3,565 1543.98,553.68 1563.83,533.83 1552.52,522.52 1532.67,542.37 1521.36,531.06 1541.21,511.21 1510,480 1510,456 1481.93,456 1481.93,440 1510,440 1510,424 1481.93,424 1481.93,408 1510,408 1510,392 1481.93,392 1481.93,376 1510,376 1510,360 1481.93,360 1481.93,344 1510,344 1510,328 1481.93,328 1481.93,312 1510,312 1510,145 1530,125 J3.1 J3.1@1647.5,127.5
TX3: J3.2 R9.1 U1.42 | length 2040
  Top Layer w8: U1.42 1318.26,1077.95 1339.47,1099.17 1376.22,1099.17 1431.84,1043.55 1508.39,1043.55 1564.08,987.87 1564.08,922.87 1619.08,867.87 1619.08,740.92 1630,730 1730,730 1740,720 R9.1@1740,695 ; J3.2 1545,275 1535,285 1535,318 1563.5,318 1563.5,334 1535,334 1535,350 1563.5,350 1563.5,366 1535,366 1535,382 1563.5,382 1563.5,398 1535,398 1535,414 1563.5,414 1563.5,430 1535,430 1535,470 1552.77,487.77 1572.93,467.62 1584.24,478.93 1564.09,499.09 1575.4,510.4 1595.56,490.25 1606.87,501.56 1586.72,521.72 1615,550 1632,550 1632,521.5 1648,521.5 1648,578.5 1664,578.5 1664,521.5 1680,521.5 1680,578.5 1696,578.5 1696,550 1720,550 1740,570 1740,615 1711.5,615 1711.5,631 1740,631 R9.1
TXD0: J4.6 U1.53 | length 924.5
  Top Layer w8: J4.6 810.31,1635.31 810.31,1496.33 785.31,1471.33 785.31,1263.3 813.91,1234.69 855,1234.69 910,1179.69 956.09,1179.69 990.47,1145.31 1070,1145.31 1081.1,1134.2 U1.53
VDD_IO: C5.1 C6.1 C15.1 C29.1 IO-3V.1 J4.5 LK1.1 LK2.1 LK3.1 LK4.1 P1.2 R1.1 R11.1 R15.1 R16.1 R17.1 U1.3 U2.8 U4.1 | length 4319.7
  Top Layer w10: IO-3V.1 845,985 923.98,985 938.98,1000 940,1000 978.58,1038.58 U1.3
  Top Layer w20: U2.8 80,855 105,830 275,830 305,860 P1.2 425,780 339.25,694.25 339.25,544.78 350,534.03 v1(350,500) ; U2.8@80,920 C15.1 80,1045 94.06,1059.06 114.47,1059.06 135,1079.58 135,1110 LK4.1 ; v1(230,1265) 230,1270 232.6,1272.6 R17.1 ; v1(250,1145) 285,1145 320,1180 515,1180 v1(520,1185) ; U4.1@460,1605 460,1640 465,1635 545,1635 545,1625 C29.1@550,1620 ; C29.1@545,1620 C29.1 C29.1@550,1620 ; R16.1 700,1390 ; v1(740,1580) 715,1580 705,1570 705,1532.4 R11.1 R11.1@695,1525 ; R1.1 847.6,872.4 v1(850,870) ; IO-3V.1 805,1000 792.4,1012.6 C6.1 C5.1 642.4,1012.6 v1(625,1030) v1(625,1205) 625,1213.09 700,1288.09 700,1390 ; v1(900,1670) 995,1670 J4.5 ; C29.1@550,1620 574.06,1620 584.06,1610 584.06,1585.53 590,1579.58 590,1545 595,1540 R15.1 645,1540 660,1525 R11.1@695,1525 ; R11.1@695,1525 700,1520 700,1478.57 700.47,1478.09 700.47,1452.38 700,1451.91 700,1390
  Bottom Layer w20: LK1.1@80,500 LK2.1 ; LK2.1@180,500 LK3.1 ; v1(230,1265) 170,1205 LK4.1 v1(250,1145) ; LK3.1@280,500 v1(350,500) ; v1(520,1185) 540,1205 v1(625,1205) ; v1(625,1030) 640,1015 705,1015 v1(850,870) ; v1(740,1580) 745.47,1574.53 879.53,1574.53 900,1595 v1(900,1670)
VDD_OSC: C1.1 C2.1 OSC-1V8.1 U1.33 | length 259.2
  Top Layer w10: U1.33 1320.32,900.79 1335,886.11 1335,885
  Top Layer w20: 1335.98,885 1335.98,873.28 1366.67,842.6 C1.1 ; C1.1@1407.6,842.6 C2.1 1480,795 OSC-1V8.1@1475,790
VDD_TX: C9.1 C10.1 TX-3V.1 U1.39 | length 354.5
  Top Layer w10: U1.39 1353.9,1018.9 v1(1360,1025) v1@1362.19,1027.19
  Top Layer w20: v1(1435,1075) TX-3V.1
  Bottom Layer w20: v1(1360,1025) 1368.09,1025 1391.69,1048.6 1391.69,1060 1406.69,1075 v1(1435,1075)
VDDA: C3.1 C4.1 U1.28 VDDA-3V.1 | length 305.7
  Top Layer w10: U1.28 1277.95,777.05 1285,770 1295.14,770
  Top Layer w20: 1295.14,767.95 1313.09,750 1355,750 1365,740 C3.1@1405,740 ; C3.1 C3.1@1405,740 ; VDDA-3V.1@1545,740 1542.4,737.4 C4.1 1407.6,737.4 C3.1@1405,740
VDDD0: C7.1 C8.1 U1.1 VDDD0-1V8.1 | length 254.3
  Top Layer w10: C7.1@920,1135 950,1135 965,1120 965,1085 972.05,1077.95 U1.1
  Top Layer w20: VDDD0-1V8.1 C8.1 907.4,1132.4 C7.1@910,1135
VIN: C30.1 D2.2 F1.1 J4.1 R18.1 R19.1 U4.8 | length 2812
  Top Layer w18: R19.1 125,1315 ; R18.1 115,1465 125,1455 125,1315 ; 462.4,1247.4 C30.1 U4.8@462.4,1407.6 ; v1(520,1245) 455,1245 440,1230 175,1230 125,1280 125,1315 ; v1(660,1205) 740,1285 v1(740,1475) ; v1(850,1530) 1645,1530 1670,1555 1675,1555
  Top Layer w50: J4.1 1675,1560 F1.1 1830,1405 D2.2
  Bottom Layer w18: v1(520,1245) 626.68,1245 660,1211.68 v1(660,1205) ; v1(740,1475) 795,1530 v1(850,1530)
pads on no net: U1.4 U1.5 U1.6 U1.7 U1.8 U1.11 U1.12 U1.19 U1.20 U1.21 U1.22 U1.26 U1.31 U1.32 U1.35 U1.55 U1.56 U1.C1 U1.C2 U1.C3 U1.C4 X1.M1 X1.M2

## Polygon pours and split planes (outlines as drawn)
DGND on Top Layer "Top - DGND-VSS_RTD" (solid, remove dead copper, pour order 19): 1025,800 1275,800 1275,400 675,400 675,500 475,500 475,675 1025,675
DGND on Top Layer "Top - DGND-VSS_IO" (solid, remove dead copper, pour order 13): 25,1225 600,1225 600,1650 700,1650 700,1175 1000,1175 1000,700 450,700 450,500 325,500 325,25 150,25 25,150
DGND on Top Layer "Top - DGND-VSS_TX" (solid, remove dead copper, pour order 17): 350,25 1750,25 1750,825 1625,825 1625,900 1425,900 1425,1200 1300,1200 1300,375 650,375 650,475 350,475
DGND on Top Layer "Top - DGND-VSS_OSC" (solid, remove dead copper, pour order 21): 950,1500 1725,1500 1725,975 1625,975 1625,925 1450,925 1450,1225 1325,1225 1325,1300 950,1300
DGND on Top Layer "Top - DGND" (solid, remove dead copper, pour order 15): 25,1250 575,1250 575,1675 725,1675 725,1200 1025,1200 1025,1135 1275,1135 1275,1275 925,1275 925,1525 1750,1525 1750,950 1650,950 1650,850 1775,850 1775,25 1975,25 2100,150 2100,1750 1975,1875 150,1875 25,1750
DGND on Bottom Layer "Bot - DGND-VSS_RTD" (solid, remove dead copper, pour order 20): 1025,800 1275,800 1275,400 675,400 675,500 475,500 475,675 1025,675
DGND on Bottom Layer "Bot - DGND-VSS_IO" (solid, remove dead copper, pour order 14): 25,1225 600,1225 600,1650 700,1650 700,1175 1000,1175 1000,700 450,700 450,500 325,500 325,25 150,25 25,150
DGND on Bottom Layer "Bot - DGND-VSS_TX" (solid, remove dead copper, pour order 18): 350,25 1750,25 1750,825 1625,825 1625,900 1425,900 1425,1200 1300,1200 1300,375 650,375 650,475 350,475
DGND on Bottom Layer "Bot - DGND-VSS_OSC" (solid, remove dead copper, pour order 22): 950,1500 1725,1500 1725,975 1625,975 1625,925 1450,925 1450,1225 1300,1225 1300,1300 950,1300
DGND on Bottom Layer "Bot - DGND" (solid, remove dead copper, pour order 16): 25,1250 575,1250 575,1675 725,1675 725,1200 1025,1200 1025,825 1275,825 1275,1275 925,1275 925,1525 1750,1525 1750,950 1650,950 1650,850 1775,850 1775,25 1975,25 2100,150 2100,1750 1975,1875 150,1875 25,1750

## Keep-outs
Top Layer:
  lines w5: 850,0 cw(c1065,0) 1280,0
Bottom Layer:
  lines w5: 850,0 cw(c1065,0) 1280,0

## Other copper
Top Layer:
  text "TOP" at 2105,310 h60 r90
Bottom Layer:
  text "BOT" at 2105,415 h60 r90

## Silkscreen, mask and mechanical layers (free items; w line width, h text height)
Bottom Overlay:
  circle w7.87: c1014.07,1095.18 r68.9
  region: 1206.82,628.53 1218.35,600.69 1246.19,589.16 1767.85,589.16 1795.69,600.69 1807.22,628.53 1807.22,717.11 1795.69,744.95 1767.85,756.48 1246.19,756.48 1218.35,744.95 1206.82,717.11
  lines w10: 457.57,1261.39 457.57,1586.39 1257.57,1586.39 1282.57,1586.39 1282.57,1261.39 457.57,1261.39
  lines w11.81: 448.2,750.78 448.2,575.78 598.2,575.78 ; 448.2,750.97 598.2,750.97 748.2,750.97 898.2,750.97 ; 598.2,750.78 598.2,575.78 ; 748.2,750.78 748.2,575.78 ; 898.2,750.78 898.2,575.78 748.2,575.78 ; 598.2,575.78 748.2,575.78
  text "SERIAL NUMBER" at 1182.57,1386.39 h88.58
  text "C    2014" at 1037.48,1065.28 h78.74
  text "AGRIGEL" at 1715,1040 h137.8
  text ".PCB_TITLE" at 1730,920 h100
  text ".Version" at 1505,810 h100
  text "VER" at 1730,810 h100
  text "MOD:" at 1146.27,637.27 h88.58
  text "ISSUE:" at 2091.27,632.27 h88.58
  text "C" at 568.28,614.79 h137.8
  text "B" at 710.01,614.79 h137.8
  text "A" at 867.49,614.79 h137.8
ACAD Top:
  circle w2: c1062.99,0 r177.17
  lines w2: 39.37,157.48 275.59,157.48 ; 39.37,1732.28 275.59,1732.28 ; 157.48,39.37 157.48,275.59 ; 157.48,1614.17 157.48,1850.39 ; 988.19,0 1062.99,0 ; 1062.99,-43.31 1062.99,0 ; 1062.99,31.5 1062.99,0 ; 1141.73,0 1062.99,0 ; 1850.39,1732.28 2086.61,1732.28 ; 1854.33,157.48 2090.55,157.48 ; 1968.5,1614.17 1968.5,1850.39 ; 1972.44,39.37 1972.44,275.59 ; 0,0 2125.98,0 2125.98,1889.76 0,1889.76 0,0
Board:
  the board outline again, w2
